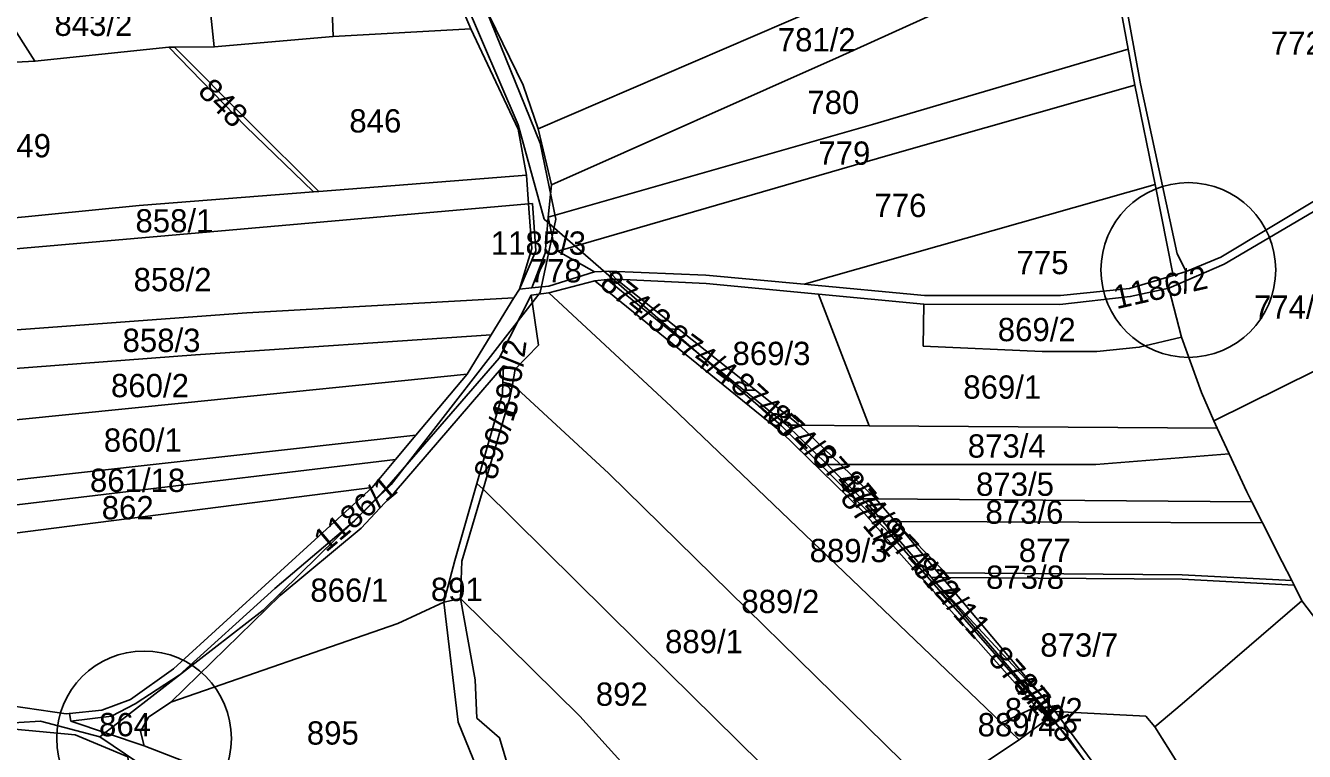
# Model space of a CAD drawing. Extents: x -623250 to -619626, y -1079612 to -1075424.
# Drawn here: x -621038 to -620489, y -1077608 to -1077297 of the extents above; entities that cross this region are included whole.
import ezdxf

# ---------------------------------------------------------------- set-up
doc = ezdxf.new("R2010")
doc.units = 0
for name, color, linetype in [('Bodové pole k revizi', 7, 'Continuous'), ('Cestní síť', 7, 'Continuous'), ('Hranice převzatá (KoPÚ Hrušová)', 7, 'Continuous'), ('Hranice šetřená (k_ú_Džbánov - vnitřní obvod)', 7, 'Continuous'), ('Katastrální hranice', 7, 'Continuous'), ('Parcela nároku', 7, 'Continuous'), ('Parcelní číslo', 7, 'Continuous'), ('Vodní toky', 7, 'Continuous')]:
    doc.layers.add(name, color=color, linetype=linetype)

msp = doc.modelspace()

# ---------------------------------------------------------------- linework, layer by layer
at = {"layer": 'Bodové pole k revizi'}
for centre in [(-620538.91, -1077401.49), (-620987.23, -1077602.53)]:
    msp.add_circle(centre, 37.5, dxfattribs=at)
at = {"layer": 'Cestní síť'}
for p, q in [((-620817.17, -1077347.1), (-620860.93, -1077239.33)), ((-620810.44, -1077379.66), (-620817.17, -1077347.1)), ((-620817.17, -1077411.1), (-620810.44, -1077379.66)), ((-620881.13, -1077493.61), (-620817.17, -1077411.1)), ((-620936.11, -1077547.5), (-620881.13, -1077493.61)), ((-621006.18, -1077601.9), (-620936.11, -1077547.5)), ((-621031.76, -1077595.09), (-621068.94, -1077597.33)), ((-621006.18, -1077601.9), (-621031.76, -1077595.09)), ((-620983.73, -1077616.96), (-621006.18, -1077601.9))]:
    msp.add_line(p, q, dxfattribs=at)
at = {"layer": 'Hranice převzatá (KoPÚ Hrušová)'}
msp.add_lwpolyline([(-620455.44, -1077430.38), (-620528, -1077466.25), (-620526.56, -1077469.33), (-620521.38, -1077480.43), (-620513.75, -1077496.75), (-620511.63, -1077500.95), (-620507.08, -1077509.95), (-620498.58, -1077526.77), (-620494.52, -1077534.8), (-620493.54, -1077536.74), (-620490.13, -1077543.5), (-620431.47, -1077620.42)], dxfattribs=at)
at = {"layer": 'Hranice šetřená (k_ú_Džbánov - vnitřní obvod)'}
msp.add_lwpolyline([(-621137.93, -1077526.56), (-621013.62, -1077510.68), (-620889.32, -1077494.81), (-620974.53, -1077572.67), (-620993.03, -1077585.83), (-621005.43, -1077590.39), (-621019.28, -1077591.79), (-621020.65, -1077591.93), (-621044.21, -1077588.56), (-621076.8, -1077589.54), (-621080.62, -1077591.04), (-621080.27, -1077594.73)], dxfattribs=at)
at = {"layer": 'Katastrální hranice'}
for p, q in [((-620541.63, -1077587.67), (-620490.13, -1077543.5)), ((-620553.25, -1077597.63), (-620541.63, -1077587.67)), ((-620453.81, -1077755.63), (-620553.25, -1077597.63))]:
    msp.add_line(p, q, dxfattribs=at)
at = {"layer": 'Parcela nároku'}
for points in [[(-620686.15, -1077230.15), (-620783.8, -1077270.52), (-620839.03, -1077292.21), (-620824.5, -1077322.12), (-620818.03, -1077340.86), (-620698.27, -1077289.33), (-620578.2, -1077237.62), (-620588.31, -1077189.72)], [(-620456.45, -1077205.38), (-620384.64, -1077305.72), (-620422.26, -1077333.77), (-620462.8, -1077358.64), (-620524.9, -1077396.04), (-620539.81, -1077402.16), (-620543.64, -1077394.52), (-620559.44, -1077321.56), (-620568.57, -1077271.31)], [(-620698.27, -1077289.33), (-620578.2, -1077237.62), (-620573.82, -1077257.79), (-620688.76, -1077310.04), (-620812.33, -1077364.99), (-620818.03, -1077340.86)], [(-620564.8, -1077306.77), (-620573.82, -1077257.79), (-620688.76, -1077310.04), (-620812.33, -1077364.99), (-620813.72, -1077378.79), (-620674.53, -1077339)], [(-620937.13, -1077272.7), (-620907.16, -1077270.11), (-620906.02, -1077301.21), (-620957.12, -1077305.77), (-620960.48, -1077274.17)], [(-620846.99, -1077297.92), (-620858.19, -1077271.52), (-620907.16, -1077270.11), (-620906.02, -1077301.21)], [(-620960.48, -1077274.17), (-620957.12, -1077305.77), (-620974.2, -1077305.88), (-620976.64, -1077305.9), (-621034.08, -1077311.92), (-621045.83, -1077293.38), (-621058.93, -1077294.62), (-621059.63, -1077283.02)], [(-621058.93, -1077294.62), (-621045.83, -1077293.38), (-621034.08, -1077311.92), (-621061.52, -1077313.33), (-621059.63, -1077283.02)], [(-620906.02, -1077301.21), (-620957.12, -1077305.77), (-620974.2, -1077305.88), (-620941.77, -1077338.32), (-620912.16, -1077367.75), (-620823.05, -1077360.77), (-620826.68, -1077340.99), (-620846.99, -1077297.92)], [(-620914.47, -1077367.93), (-620943.73, -1077339.72), (-620976.64, -1077305.9), (-621034.08, -1077311.92), (-621061.52, -1077313.33), (-621128.23, -1077317.38), (-621130.34, -1077357.73), (-621129.24, -1077387.69), (-620989.35, -1077373.8)], [(-620974.2, -1077305.88), (-620976.64, -1077305.9), (-620943.73, -1077339.72), (-620914.47, -1077367.93), (-620912.16, -1077367.75), (-620941.77, -1077338.32)], [(-620422.26, -1077333.77), (-620371.95, -1077302.9), (-620370.5, -1077305.13), (-620372.79, -1077306.58), (-620460.93, -1077362.28), (-620523.52, -1077399.04), (-620547.34, -1077409.36), (-620563.83, -1077412.93), (-620594.08, -1077416.27), (-620652.47, -1077416.15), (-620697.72, -1077411.88), (-620745.96, -1077407.32), (-620784.54, -1077405.49), (-620787.68, -1077402.01), (-620746, -1077403.66), (-620703.91, -1077407.59), (-620652.15, -1077412.42), (-620593.85, -1077412.5), (-620564.2, -1077409.47), (-620545.47, -1077403.86), (-620539.81, -1077402.16), (-620524.9, -1077396.04), (-620462.8, -1077358.64)], [(-620561.83, -1077322.1), (-620564.8, -1077306.77), (-620674.53, -1077339), (-620813.72, -1077378.79), (-620811.5, -1077389.65), (-620809.66, -1077393.34), (-620667.87, -1077352.4)], [(-620553.21, -1077364.79), (-620561.83, -1077322.1), (-620667.87, -1077352.4), (-620809.66, -1077393.34), (-620793.81, -1077402.33), (-620787.68, -1077402.01), (-620746, -1077403.66), (-620703.91, -1077407.59)], [(-620914.47, -1077367.93), (-620912.16, -1077367.75), (-620823.05, -1077360.77), (-620822.16, -1077373.13), (-620976.74, -1077386.72), (-621130.91, -1077400.13), (-621130.43, -1077396.55), (-621129.24, -1077387.69), (-620989.35, -1077373.8)], [(-620703.91, -1077407.59), (-620553.21, -1077364.79), (-620545.47, -1077403.86), (-620564.2, -1077409.47), (-620593.85, -1077412.5), (-620652.15, -1077412.42)], [(-620460.93, -1077362.28), (-620428.6, -1077413.64), (-620455.44, -1077430.38), (-620528, -1077466.25), (-620533.24, -1077454.08), (-620541.8, -1077430.35), (-620547.34, -1077409.36), (-620523.52, -1077399.04)], [(-620976.74, -1077386.72), (-620822.16, -1077373.13), (-620820.79, -1077392.25), (-620826.11, -1077409.68), (-620828.42, -1077413.45), (-620943.11, -1077419.82), (-621133.03, -1077433.89), (-621130.91, -1077400.13)], [(-620819, -1077393.22), (-620820.5, -1077372.96), (-620822.16, -1077373.13), (-620820.79, -1077392.25), (-620826.11, -1077409.68)], [(-620813.72, -1077378.79), (-620814.97, -1077394.32), (-620820.79, -1077409.15), (-620813.52, -1077408.39), (-620793.81, -1077402.33), (-620809.66, -1077393.34), (-620811.5, -1077389.65)], [(-620820.79, -1077409.15), (-620813.52, -1077408.39), (-620793.81, -1077402.33), (-620787.68, -1077402.01), (-620784.54, -1077405.49), (-620788.48, -1077405.57), (-620793.78, -1077406.21), (-620813.41, -1077411.33), (-620821.08, -1077412.33), (-620834.81, -1077439.29), (-620882.87, -1077494.73), (-620896.86, -1077509.2), (-620931.07, -1077538.23), (-620972.19, -1077575.39), (-620991.01, -1077587.68), (-621001.21, -1077592.98), (-621018.65, -1077595.12), (-621019.28, -1077591.79), (-621005.43, -1077590.39), (-620993.03, -1077585.83), (-620974.53, -1077572.67), (-620889.32, -1077494.81), (-620879.3, -1077482.89), (-620870.5, -1077472.43), (-620848.46, -1077446.22), (-620838.17, -1077429.39), (-620828.42, -1077413.45), (-620826.11, -1077409.68)], [(-620793.78, -1077406.21), (-620813.41, -1077411.33), (-620760.97, -1077460.03), (-620619.14, -1077595.91), (-620604.25, -1077588.97), (-620679.14, -1077504.78), (-620713.77, -1077470.89)], [(-620693.99, -1077485.04), (-620679.02, -1077499.68), (-620676.12, -1077502.52), (-620670.12, -1077509.45), (-620649.39, -1077533.39), (-620602.13, -1077587.98), (-620604.25, -1077588.97), (-620679.14, -1077504.78), (-620713.77, -1077470.89), (-620793.78, -1077406.21), (-620788.48, -1077405.57), (-620762.38, -1077426.72), (-620729.79, -1077453.13), (-620711.27, -1077468.13)], [(-620784.54, -1077405.49), (-620788.48, -1077405.57), (-620762.38, -1077426.72), (-620757.53, -1077426.98)], [(-620697.72, -1077411.88), (-620675.93, -1077468.33), (-620705.83, -1077468.13), (-620724.73, -1077453.09), (-620757.53, -1077426.98), (-620784.54, -1077405.49), (-620745.96, -1077407.32)], [(-620652.73, -1077434.14), (-620652.47, -1077416.15), (-620594.08, -1077416.27), (-620563.83, -1077412.93), (-620547.34, -1077409.36), (-620541.8, -1077430.35), (-620560.01, -1077434.63), (-620578.21, -1077436.52), (-620601.7, -1077436.43)], [(-620943.11, -1077419.82), (-620828.42, -1077413.45), (-620838.17, -1077429.39), (-620965.1, -1077437.87), (-621133.35, -1077450.57), (-621133.03, -1077433.89)], [(-621018.65, -1077595.12), (-621001.21, -1077592.98), (-620991.01, -1077587.68), (-620972.19, -1077575.39), (-620931.07, -1077538.23), (-620896.86, -1077509.2), (-620882.87, -1077494.73), (-620834.81, -1077439.29), (-620821.08, -1077412.33), (-620817.96, -1077433.72), (-620827.88, -1077444.11), (-620832.98, -1077442.68), (-620879.84, -1077497.09), (-620894.02, -1077512.32), (-620928.8, -1077541.25), (-620975.69, -1077586.93), (-620985.33, -1077593.45), (-620988.73, -1077599.5), (-620987.2, -1077605.73)], [(-620611.54, -1077603.19), (-620619.14, -1077595.91), (-620760.97, -1077460.03), (-620813.41, -1077411.33), (-620821.08, -1077412.33), (-620817.96, -1077433.72), (-620827.88, -1077444.11), (-620829.07, -1077450.57), (-620787.71, -1077488.88), (-620646.97, -1077626.81)], [(-620560.01, -1077434.63), (-620541.8, -1077430.35), (-620533.24, -1077454.08), (-620528, -1077466.25), (-620526.56, -1077469.33), (-620675.93, -1077468.33), (-620697.72, -1077411.88), (-620652.47, -1077416.15), (-620652.73, -1077434.14), (-620601.7, -1077436.43), (-620578.21, -1077436.52)], [(-620724.73, -1077453.09), (-620757.53, -1077426.98), (-620762.38, -1077426.72), (-620729.79, -1077453.13)], [(-620965.1, -1077437.87), (-621133.35, -1077450.57), (-621133.77, -1077471.92), (-621134.06, -1077475.73), (-621090.84, -1077470.67), (-620969.74, -1077458.47), (-620848.46, -1077446.22), (-620838.17, -1077429.39)], [(-620894.02, -1077512.32), (-620928.8, -1077541.25), (-620975.69, -1077586.93), (-620878.3, -1077553.15), (-620858.57, -1077544.04), (-620853.88, -1077526.11), (-620844.37, -1077493.12), (-620833.29, -1077454.71), (-620833.16, -1077449.64), (-620832.98, -1077442.68), (-620879.84, -1077497.09)], [(-620832.98, -1077442.68), (-620827.88, -1077444.11), (-620829.07, -1077450.57), (-620833.16, -1077449.64)], [(-621134.06, -1077475.73), (-621136.16, -1077503.29), (-621037.15, -1077491), (-620870.5, -1077472.43), (-620848.46, -1077446.22), (-620969.74, -1077458.47), (-621090.84, -1077470.67)], [(-620833.29, -1077454.71), (-620833.16, -1077449.64), (-620829.07, -1077450.57), (-620830.13, -1077456.35), (-620841.72, -1077495.6), (-620844.37, -1077493.12)], [(-620787.71, -1077488.88), (-620829.07, -1077450.57), (-620830.13, -1077456.35), (-620841.72, -1077495.6), (-620762.03, -1077574.2), (-620682.61, -1077652.52), (-620646.97, -1077626.81)], [(-620705.83, -1077468.13), (-620724.73, -1077453.09), (-620729.79, -1077453.13), (-620711.27, -1077468.13)], [(-620688.25, -1077485.04), (-620705.83, -1077468.13), (-620711.27, -1077468.13), (-620693.99, -1077485.04)], [(-620675.93, -1077468.33), (-620526.56, -1077469.33), (-620521.38, -1077480.43), (-620578.67, -1077485.03), (-620688.25, -1077485.04), (-620705.83, -1077468.13)], [(-621037.15, -1077491), (-620870.5, -1077472.43), (-620879.3, -1077482.89), (-621008.27, -1077498.31), (-621136.94, -1077513.55), (-621136.16, -1077503.29)], [(-620578.67, -1077485.03), (-620521.38, -1077480.43), (-620513.75, -1077496.75), (-620511.63, -1077500.95), (-620673.03, -1077499.68), (-620688.25, -1077485.04)], [(-621008.27, -1077498.31), (-621136.94, -1077513.55), (-621137.93, -1077526.56), (-621013.72, -1077510.66), (-620889.32, -1077494.81), (-620879.3, -1077482.89)], [(-620693.99, -1077485.04), (-620688.25, -1077485.04), (-620673.03, -1077499.68), (-620679.02, -1077499.68)], [(-620841.72, -1077495.6), (-620844.37, -1077493.12), (-620853.88, -1077526.11), (-620858.57, -1077544.04), (-620851.45, -1077542.42), (-620850.82, -1077526.41)], [(-620762.03, -1077574.2), (-620841.72, -1077495.6), (-620850.82, -1077526.41), (-620851.45, -1077542.42), (-620800.08, -1077592.94), (-620718.81, -1077682.81), (-620682.61, -1077652.52)], [(-620673.03, -1077499.68), (-620679.02, -1077499.68), (-620676.12, -1077502.52), (-620670.12, -1077509.45), (-620664.81, -1077509.43)], [(-620511.63, -1077500.95), (-620507.08, -1077509.95), (-620664.81, -1077509.43), (-620673.03, -1077499.68)], [(-620664.81, -1077509.43), (-620670.12, -1077509.45), (-620649.39, -1077533.39), (-620644.59, -1077533.42)], [(-620643.22, -1077531.53), (-620541.5, -1077532.38), (-620494.52, -1077534.8), (-620493.54, -1077536.74), (-620541.57, -1077534.13), (-620644.59, -1077533.42), (-620664.81, -1077509.43)], [(-620507.08, -1077509.95), (-620498.58, -1077526.77), (-620494.52, -1077534.8), (-620541.5, -1077532.38), (-620643.22, -1077531.53), (-620664.81, -1077509.43)], [(-620649.39, -1077533.39), (-620599.6, -1077586.8), (-620602.13, -1077587.98)], [(-620644.59, -1077533.42), (-620649.39, -1077533.39), (-620599.6, -1077586.8)], [(-620493.54, -1077536.74), (-620490.13, -1077543.5), (-620541.63, -1077587.67), (-620553.25, -1077597.63), (-620557.23, -1077593.02), (-620596.08, -1077590.97), (-620599.6, -1077586.8), (-620644.59, -1077533.42), (-620541.57, -1077534.13)], [(-620852.4, -1077595.58), (-620858.57, -1077544.04), (-620878.3, -1077553.15), (-620975.69, -1077586.93), (-620985.33, -1077593.45), (-620988.73, -1077599.5), (-620987.2, -1077605.73), (-620932.29, -1077627.05), (-620895.94, -1077632.9), (-620870.4, -1077635.97), (-620857.77, -1077638.01), (-620839.72, -1077640.92), (-620829.32, -1077644.28), (-620836.97, -1077633.47)], [(-620844.37, -1077593.81), (-620845.11, -1077577.39), (-620851.45, -1077542.42), (-620858.57, -1077544.04), (-620852.4, -1077595.58), (-620836.97, -1077633.47), (-620829.32, -1077644.28), (-620839.72, -1077640.92), (-620857.77, -1077638.01), (-620840.42, -1077643.71), (-620821.25, -1077651.89), (-620773.73, -1077696.26), (-620757.71, -1077713.72), (-620685.44, -1077756.32), (-620743.55, -1077716.58), (-620798.58, -1077671.35), (-620822.67, -1077642.69), (-620834.66, -1077602.26)], [(-620718.81, -1077682.81), (-620800.08, -1077592.94), (-620851.45, -1077542.42), (-620845.11, -1077577.39), (-620844.37, -1077593.81), (-620834.66, -1077602.26), (-620822.67, -1077642.69), (-620798.58, -1077671.35), (-620743.55, -1077716.58), (-620685.44, -1077756.32), (-620662.26, -1077773.11), (-620654.94, -1077775.38), (-620619.25, -1077805.5), (-620545.44, -1077749.25), (-620507, -1077808.5), (-620479.44, -1077797.32), (-620501.31, -1077742.94), (-620532.98, -1077681.37), (-620584.3, -1077610.83), (-620597.88, -1077593.11), (-620611.54, -1077603.19), (-620646.97, -1077626.81), (-620682.61, -1077652.52)], [(-620602.02, -1077591.48), (-620604.25, -1077588.97), (-620619.14, -1077595.91), (-620611.54, -1077603.19), (-620597.88, -1077593.11), (-620599.32, -1077591.23)], [(-620604.25, -1077588.97), (-620602.13, -1077587.98), (-620599.32, -1077591.23), (-620602.02, -1077591.48)], [(-620596.08, -1077590.97), (-620599.6, -1077586.8), (-620602.13, -1077587.98), (-620599.32, -1077591.23)], [(-620530.46, -1077679.74), (-620498.61, -1077741.4), (-620477.3, -1077796.45), (-620479.44, -1077797.32), (-620501.31, -1077742.94), (-620532.98, -1077681.37), (-620584.3, -1077610.83), (-620597.88, -1077593.11), (-620599.32, -1077591.23), (-620596.08, -1077590.97)], [(-620553.25, -1077597.63), (-620557.23, -1077593.02), (-620596.08, -1077590.97), (-620530.46, -1077679.74), (-620498.61, -1077741.4), (-620477.3, -1077796.45), (-620442.63, -1077782.38), (-620453.81, -1077755.63)]]:
    msp.add_lwpolyline(points, close=True, dxfattribs=at)
for points in [[(-620568.57, -1077271.31), (-620559.44, -1077321.56), (-620543.64, -1077394.52), (-620539.81, -1077402.16), (-620545.47, -1077403.86), (-620553.21, -1077364.79), (-620561.83, -1077322.1), (-620564.8, -1077306.77), (-620573.82, -1077257.79)], [(-620839.03, -1077292.21), (-620824.5, -1077322.12), (-620818.03, -1077340.86), (-620812.33, -1077364.99), (-620813.72, -1077378.79), (-620814.97, -1077394.32), (-620820.79, -1077409.15), (-620826.11, -1077409.68), (-620819, -1077393.22), (-620820.5, -1077372.96), (-620822.16, -1077373.13), (-620823.05, -1077360.77), (-620826.68, -1077340.99), (-620846.99, -1077297.92), (-620858.19, -1077271.52)], [(-621137.93, -1077526.56), (-621013.72, -1077510.66), (-620889.32, -1077494.81), (-620974.53, -1077572.67), (-620993.03, -1077585.83), (-621005.43, -1077590.39), (-621019.28, -1077591.79), (-621020.65, -1077591.93), (-621044.21, -1077588.56)], [(-621044.21, -1077588.56), (-621020.65, -1077591.93), (-621019.28, -1077591.79), (-621018.65, -1077595.12), (-620987.2, -1077605.73), (-620932.29, -1077627.05)], [(-621042.92, -1077598.61), (-621016.76, -1077601.01), (-620994.15, -1077610.5), (-620992.91, -1077621.62), (-621008.82, -1077651.88), (-621032.36, -1077672.8), (-621038.22, -1077689.94)], [(-620994.15, -1077610.5), (-621016.76, -1077601.01), (-621042.92, -1077598.61)]]:
    msp.add_lwpolyline(points, dxfattribs=at)
at = {"layer": 'Vodní toky'}
for p, q in [((-620826.67, -1077339.21), (-620872.43, -1077232.6)), ((-620815.49, -1077379.61), (-620826.67, -1077339.21)), ((-620815.49, -1077379.61), (-620713.52, -1077468.37)), ((-620713.52, -1077468.37), (-620667.95, -1077513.78)), ((-620667.95, -1077513.78), (-620590.07, -1077602.73)), ((-620590.07, -1077602.73), (-620530.12, -1077687.19))]:
    msp.add_line(p, q, dxfattribs=at)

# ---------------------------------------------------------------- texts
at = {"layer": 'Parcelní číslo'}
for s, p in [('843/2', (-621025.7, -1077301.02)), ('781/2', (-620715.17, -1077307.68)), ('772/2', (-620503.51, -1077309.14)), ('780', (-620702.47, -1077334.54)), ('846', (-620899.1, -1077342.48)), ('849', (-621049.5, -1077353.14)), ('779', (-620697.75, -1077356.33)), ('776', (-620673.68, -1077378.78)), ('858/1', (-620990.92, -1077385.39)), ('1185/3', (-620838.36, -1077394.95)), ('775', (-620612.66, -1077403.3)), ('778', (-620821.61, -1077406.82)), ('858/2', (-620991.73, -1077410.61)), ('774/2', (-620510.76, -1077422.41)), ('858/3', (-620996.46, -1077436.68)), ('869/2', (-620620.72, -1077432.05)), ('869/3', (-620734.59, -1077442.3)), ('860/2', (-621001.43, -1077456.09)), ('869/1', (-620635.53, -1077456.74)), ('860/1', (-621004.49, -1077479.5)), ('873/4', (-620633.6, -1077482.02)), ('861/18', (-621010.46, -1077496.76)), ('873/5', (-620630.06, -1077498.42)), ('862', (-621005.4, -1077508.52)), ('873/6', (-620626.03, -1077510.41)), ('889/3', (-620701.48, -1077526.9)), ('877', (-620611.7, -1077526.82)), ('873/8', (-620625.75, -1077538.33)), ('866/1', (-620915.85, -1077543.9)), ('891', (-620864.11, -1077543.57)), ('889/2', (-620730.81, -1077548.75)), ('889/1', (-620763.57, -1077565.96)), ('873/7', (-620602.48, -1077567.44)), ('892', (-620793.28, -1077588.55)), ('871/2', (-620617.72, -1077595.17)), ('889/4', (-620629.37, -1077601.66)), ('864', (-621006.58, -1077601.62)), ('895', (-620917.35, -1077605.19))]:
    msp.add_text(s, height=10, dxfattribs=at).set_placement(p)
for s, rotation, p in [('848', 315, (-620964.63, -1077325.34)), ('874/3', 321.2606, (-620792.26, -1077408.32)), ('1186/2', 12.8581, (-620569.79, -1077418.34)), ('874/4', 323.5991, (-620764.29, -1077431.81)), ('890/2', 82.1199, (-620827.53, -1077465.18)), ('874/5', 317.5963, (-620736.11, -1077451.77)), ('874/6', 317.4657, (-620720.56, -1077465.35)), ('890/1', 73.434, (-620836.33, -1077492.13)), ('874/7', 311.8779, (-620701, -1077481.79)), ('1186/1', 40.0271, (-620909.12, -1077522.96)), ('874/9', 309.8056, (-620689.27, -1077492.73)), ('871/1', 310.4573, (-620688.85, -1077499.82)), ('874/12', 313.2068, (-620671.38, -1077515.58)), ('874/11', 311.9413, (-620657.77, -1077530.01)), ('874/10', 311.4923, (-620625.36, -1077568.53)), ('874/8', 310.4888, (-620614.73, -1077579.71))]:
    msp.add_text(s, height=10, rotation=rotation, dxfattribs=at).set_placement(p)

doc.saveas('drawing.dxf')
